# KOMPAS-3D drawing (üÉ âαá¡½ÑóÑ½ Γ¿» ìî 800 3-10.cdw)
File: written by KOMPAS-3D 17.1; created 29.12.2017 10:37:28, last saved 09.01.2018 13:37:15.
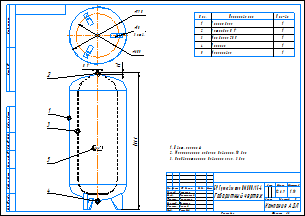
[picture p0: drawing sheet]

Sheet 1: A3, landscape, title-block layout from C:\Лощинин\GRAPHIC.LYT style 1

Title block, sheet 1: name: БР Гранлевел тип НМ 800/1,5-6 / Габаритный чертеж; mass: 126,9; sheets: 1; sheet format: A3; stored path: \\Fsk1\files\АП\20_PKO\02_Насосное направление\Разработка\04_Проекты разные\Баки\КД действующая\Баки Flexcon R\Компас\Чертежи\БР Гранлевел тип НМ 800 1,5-6.cdw; drawn by: Лощинин; checked by: Хантимеров

Views: Проекционный вид 4, Проекционный вид 5
Referenced files in K:\АП\20_PKO\02_Насосное направление\Разработка\04_Проекты разные\Баки\КД действующая\Баки Flexcon R\Компас\: 16802_Flexcon_800_1-6.m3d
Referenced files in C:\Лощинин\: GRAPHIC.LYT
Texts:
  IvAn
  ADL
  Поз.
  Кол-во
  Корпус бака
  Мембрана SBR
  Патрубок G 1"
  Ниппель
  Маркировка
  АДЛ
  Цвет: красный
  Максимальное рабочее давление: 10 бар
  Предварительное давление газа: 3 бар
  ACAD_ISO03W100_RGB_223_127_255_SC_0.063_THICK_0.05
  ACAD_ISO03W100_RGB_223_127_255_SC_1_THICK_0.05
  Лит-Масса-Масштаб
  Материал-Предприятие
  Масштаб
  Изм.
  Лист
  № докум.
  Подп.
  Дата
  Лит.
  Разраб.
  Пров.
  Т.контр.
  Курлыкина
  Листов
  Нач.отд.
  Щетинин
  Н.контр.
  Долгов
  Утв.
  Рашидов
  Компания АДЛ
  Изменение
  Номер документа
  Подпись
  Обозначение документа
  Наименование изделия
  Масса изделия по ГОСТ 2.109-73
  Порядковый номер листа
  Общее количество листов в документе
  Характер работы, выполненной лицом, подписавшим документ
  Наименование или индекс предприятия, выпускающего документ
  Инв. № подл.
  Подп. и дата
  Взам. инв. №
  Инв. № дубл.
  Инвентарный номер подлинника по ГОСТ 2.501-68
  Подпись принявшего подлинник в отдел технической документации
  Инвентарный номер подлинника, взамен которого выпущен данный подлинник
  Инвентарный номер дубликата по ГОСТ 2.502-68
  Подпись принявшего дубликат в отдел технической документации
  Справ. №
  Перв. примен.
  Обозначение документа, взамен или на основании которого выпущен данный документ
  Обозначение документа, в котором впервые записан данный документ
  Подпись лица, копировавшего чертеж
  Обозначение формата листа
Dimensions and other numbers on the sheet: 1; 3; 2; 4; 5; 1890; 21; 790; 605; 18; 3 отв.; 16802_Flexcon_800_1-6; 1:15; 126,9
